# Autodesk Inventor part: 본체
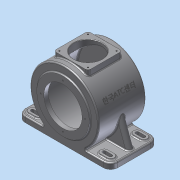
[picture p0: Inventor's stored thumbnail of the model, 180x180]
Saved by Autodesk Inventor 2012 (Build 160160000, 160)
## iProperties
Created: 2015-06
Part Number: 본체
Material: Default
Document SubType Name: Modeling
Designer: Administrator
Density: 1 g/cm^3
Author: Administrator
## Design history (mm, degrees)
sketch "스케치1"
  geometry: C1 r 85 at (0, 0); 1 further point
  constraints: 1 centre point, 1 coincident
  dimensions: "d0" = 170 diameter of C1
extrude "돌출1" new body sketch "스케치1" stored distance "d1" = 118; taper "d2" = 0 deg
node "작업 평면1"
sketch "스케치2"
  geometry: L1 (-115, 59)-(115, 59); L2 (115, 59)-(115, -59); L3 (115, -59)-(-115, -59); L4 (-115, -59)-(-115, 59); L5 (-115, -59)-(115, 59); 2 further points
  constraints: 10 end point, 2 parallel, 1 coincident, 1 horizontal, 1 midpoint, 1 perpendicular
  dimensions: "d4" = 118 distance between parallel lines of L3 L1; "d5" = 230 distance between parallel lines of L2 L4
extrude "돌출2" join sketch "스케치2" distance "d6" = 14; taper "d7" = 0 deg
node "작업 평면2"
sketch "스케치4"
  geometry: C1 r 77 at (0, 0); 1 further point
  constraints: 1 centre point, 1 coincident
  dimensions: "d12" = 154 diameter of C1
extrude "돌출4" cut sketch "스케치4" distance "d13" = 102; taper "d14" = 0 deg
sketch "스케치5"
  geometry: C1 r 65 at (0, 0); A1 r 85 centre (0, 0) between (71, 46.733) and (71, -46.733) reference
  constraints: 1 centre point, 1 coincident
  dimensions: "d15" = 130 diameter of C1
extrude "돌출5" join sketch "스케치5" distance "d16" = 3; taper "d17" = 0 deg
sketch "스케치6"
  geometry: C1 r 65 at (0, 0) reference; C2 r 47.5 at (0, 0)
  constraints: 1 centre point, 1 coincident
  dimensions: "d18" = 95 diameter of C2
extrude "돌출6" cut sketch "스케치6" distance "d19" = 11; taper "d20" = 0 deg
sketch "스케치7"
  geometry: C1 r 65 at (0, 0); A1 r 85 centre (0, 0) between (-71, -46.733) and (-71, 46.733) reference
  constraints: 1 centre point, 1 coincident
  dimensions: "d21" = 130 diameter of C1
extrude "돌출7" join sketch "스케치7" distance "d22" = 13; taper "d23" = 0 deg
sketch "스케치8"
  geometry: C1 r 77 at (0, 0) reference; C2 r 31 at (0, 0)
  constraints: 1 centre point, 1 coincident
  dimensions: "d24" = 62 diameter of C2
extrude "돌출8" join sketch "스케치8" distance "d25" = 3.5; taper "d26" = 0 deg
sketch "스케치9"
  geometry: C1 r 31 at (0, 0) reference; C2 r 23.5 at (0, 0)
  constraints: 1 centre point, 1 coincident
  dimensions: "d27" = 47 diameter of C2
extrude "돌출9" cut sketch "스케치9" distance "d28" = 14; taper "d29" = 0 deg
sketch "스케치10"
  geometry: C1 r 23.5 at (0, 0) reference; C2 r 15 at (0, 0)
  constraints: 1 centre point, 1 coincident
  dimensions: "d30" = 30 diameter of C2
extrude "돌출10" cut sketch "스케치10" distance "d31" = 3; taper "d32" = 0 deg
node "작업 평면4"
sketch "스케치11"
  geometry: L1 (-42.5, 42.5)-(42.5, 42.5); L2 (42.5, 42.5)-(42.5, -42.5); L3 (42.5, -42.5)-(-42.5, -42.5); L4 (-42.5, -42.5)-(-42.5, 42.5); L5 (-42.5, 0)-(42.5, 0); L6 (0, 42.5)-(0, -42.5); L7 (-85, 59)-(85, 59) reference; L8 (85, -59)-(85, 59) reference; 3 further points
  constraints: 12 end point, 4 midpoint, 2 parallel, 1 horizontal, 1 perpendicular
  dimensions: "d35" = 85 distance between parallel lines of L3 L1; "d36" = 85 distance between parallel lines of L2 L4; "d37" = 59 distance between parallel lines of L5 L7; "d38" = 85 distance between parallel lines of L6 L8
extrude "돌출11" join sketch "스케치11" stored distance "d39" = 3; taper "d40" = 0 deg
sketch "스케치12"
  geometry: C1 r 35 at (0, 0); 1 further point
  constraints: 1 centre point, 1 coincident
  dimensions: "d41" = 70 diameter of C1
extrude "돌출12" cut sketch "스케치12" stored distance "d42" = 3; taper "d43" = 0 deg
sketch "스케치13"
  geometry: L1 (59, -115)-(59, 115) reference; L2 (-32, 97)-(-32, 81); L3 (-50, 97)-(-50, 81); L4 (50, 97)-(50, 81); L5 (32, 97)-(32, 81); L6 (41, 115)-(41, 46.733); L7 (32, -81)-(32, -97); L8 (50, -81)-(50, -97); L9 (-32, -81)-(-32, -97); L10 (-50, -81)-(-50, -97); L11 (-41, 115)-(-41, 46.733); L12 (-41, 46.733)-(-41, -115); L13 (41, 46.733)-(41, -115); L14 (59, 115)-(-59, 115) reference; L15 (-59, 115)-(-59, -115) reference; L16 (-59, -115)-(59, -115) reference; A1 r 9 centre (-41, 97) between (-32, 97) and (-50, 97); A2 r 9 centre (-41, 81) between (-50, 81) and (-32, 81); A3 r 9 centre (41, 97) between (50, 97) and (32, 97); A4 r 9 centre (-41, -81) between (-32, -81) and (-50, -81); A5 r 9 centre (-41, -97) between (-50, -97) and (-32, -97); A6 r 9 centre (41, -81) between (50, -81) and (32, -81); A7 r 9 centre (41, -97) between (32, -97) and (50, -97); A8 r 9 centre (41, 81) between (32, 81) and (50, 81); 2 further points
  constraints: 24 end point, 16 point on circle, 11 tangent, 8 centre point, 8 point on line, 5 parallel, 4 vertical
  dimensions: "d68" = 16 distance of A2.centre A1.centre; "d69" = 16 distance of A3.centre A8.centre; "d71" = 18 distance from line of A3.centre L1; "d74" = 9 radius of A1; "d75" = 9 radius of A2; "d76" = 18 distance from line of L14 A1.centre; "d77" = 18 distance from line of A1.centre L15; "d78" = 18 distance from line of L14 A3.centre; "d79" = 9 radius of A3; "d80" = 9 radius of A8; "d81" = 9 radius of A4; "d82" = 9 radius of A5; "d84" = 16 distance of A5.centre A4.centre; "d85" = 18 distance from line of L15 A5.centre; "d86" = 9 radius of A7; "d87" = 9 radius of A6; "d88" = 16 distance of A6.centre A7.centre; "d89" = 18 distance from line of L1 A7.centre; "d91" = 18 distance from line of L16 A7.centre; "d92" = 18 distance from line of L16 A5.centre
extrude "돌출13" join sketch "스케치13" distance "d93" = 3; taper "d94" = 0 deg
sketch "스케치14"
  geometry: L1 (-32, 97)-(-32, 81) reference; L2 (-50, 81)-(-50, 97) reference; L3 (-32, -81)-(-32, -97) reference; L4 (-50, -97)-(-50, -81) reference; L5 (50, -81)-(50, -97) reference; L6 (32, -97)-(32, -81) reference; L7 (-45, 97)-(-45, 81); L8 (-37, 97)-(-37, 81); L9 (37, 97)-(37, 81); L10 (45, 97)-(45, 81); L11 (-37, -81)-(-37, -97); L12 (-45, -81)-(-45, -97); L13 (37, -81)-(37, -97); L14 (45, -81)-(45, -97); L15 (-59, 115)-(59, 115) reference; L16 (-59, 46.733)-(-59, 115) reference; L17 (59, 115)-(59, 46.733) reference; L18 (59, -46.733)-(59, -115) reference; L19 (59, -115)-(-59, -115) reference; L20 (-59, -115)-(-59, -46.733) reference; A1 r 9 centre (-41, 97) between (-32, 97) and (-50, 97) reference; A2 r 9 centre (-41, -81) between (-32, -81) and (-50, -81) reference; A3 r 9 centre (-41, 81) between (-50, 81) and (-32, 81) reference; A4 r 9 centre (-41, -97) between (-50, -97) and (-32, -97) reference; A5 r 9 centre (41, -81) between (50, -81) and (32, -81) reference; A6 r 9 centre (41, -97) between (32, -97) and (50, -97) reference; A7 r 4 centre (-41, 81) between (-45, 81) and (-37, 81); A8 r 4 centre (-41, 97) between (-37, 97) and (-45, 97); A9 r 4 centre (41, 81) between (37, 81) and (45, 81); A10 r 4 centre (41, 97) between (45, 97) and (37, 97); A11 r 4 centre (-41, -97) between (-45, -97) and (-37, -97); A12 r 4 centre (-41, -81) between (-37, -81) and (-45, -81); A13 r 4 centre (41, -97) between (37, -97) and (45, -97); A14 r 4 centre (41, -81) between (45, -81) and (37, -81); 11 further points
  constraints: 16 end point, 16 point on circle, 15 tangent, 8 centre point, 8 coincident, 1 parallel
  dimensions: "d110" = 4 radius of A8; "d111" = 4 radius of A7; "d112" = 16 distance of A3.centre point (-41, 97); "d113" = 18 distance from line of L15 point (-41, 97); "d114" = 18 distance from line of L16 point (-41, 81); "d115" = 5 radial gap between concentric circles of A7 A3; "d116" = 4 radius of A10; "d117" = 4 radius of A9; "d118" = 16 distance of point (41, 97) point (41, 81); "d119" = 18 distance from line of point (41, 97) L15; "d120" = 18 distance from line of L17 point (41, 97); "d121" = 18 distance from line of L17 point (41, 81); "d122" = 4 radius of A14; "d123" = 4 radius of A13; "d124" = 18 distance from line of L18 point (41, -81); "d125" = 16 distance of point (41, -81) A6.centre; "d126" = 18 distance from line of L19 point (41, -97); "d127" = 5 radial gap between concentric circles of A6 A13; "d128" = 4 radius of A12; "d129" = 4 radius of A11; "d130" = 16 distance of point (-41, -97) point (-41, -81); "d131" = 18 distance from line of L20 point (-41, -97); "d132" = 18 distance from line of L19 point (-41, -97); "d133" = 5 radial gap between concentric circles of A2 A12
extrude "돌출14" cut sketch "스케치14" stored distance "d134" = 3; taper "d135" = 0 deg
node "작업 평면5"
sketch "스케치15"
  geometry: L1 (71, 115)-(71, 46.733) reference; L2 (85, 115)-(71, 115) reference; L3 (71, -115)-(71, -46.733) reference; L4 (85, -115)-(71, -115) reference; L5 (71, 115)-(71, 109); L6 (71, 109)-(4.703, 84.87); L7 (71, -115)-(71, -109); L8 (71, -109)-(4.703, -84.87); A1 r 85 centre (0, 0) between (71, 46.733) and (71, -46.733) reference; 1 further point
  constraints: 8 end point, 2 point on circle, 2 point on line
  dimensions: "d137" = 6 distance of L1.start L5.end; "d138" = 110 deg angle of L5 L6; "d139" = 6 distance of L3.start L7.end; "d140" = 110 deg angle of L8 L7
extrude "돌출15" join sketch "스케치15" stored distance "d141" = 15; taper "d142" = 0 deg
node "작업 평면7"
  node "작업 평면6"
sketch "스케치16"
  geometry: 2 further points
  constraints: 1 coincident, 1 other
feature "엠보싱1" sketch "스케치16" dims "d145" = 0.5, "d146" = 0
sketch "스케치17"
  geometry: L1 (42.5, 42.5)-(42.5, -42.5) reference; L2 (-42.5, 42.5)-(42.5, 42.5) reference; L3 (-35.5, 35.5)-(35.5, 35.5); L4 (35.5, 35.5)-(35.5, -35.5); L5 (35.5, -35.5)-(-35.5, -35.5); L6 (-35.5, -35.5)-(-35.5, 35.5); 4 further points
  constraints: 8 end point, 4 coincident, 2 parallel, 1 horizontal, 1 perpendicular
  dimensions: "d147" = 71 distance between parallel lines of L5 L3; "d148" = 71 distance between parallel lines of L6 L4; "d149" = 7 distance between parallel lines of L4 L1; "d150" = 7 distance between parallel lines of L3 L2
hole "구멍1" sketch "스케치17" at (-35.5, 35.5), (35.5, 35.5), (35.5, -35.5), (-35.5, -35.5) diameter "d151" = 3.242; stored, may be unused: countersink angle "d155" = 90 deg, drill point angle "d157" = 118 deg; dims "d152" = 10, "d153" = 4, "d154" = 2, "d156" = 13
sketch "스케치18"
  geometry: L1 (0, 55)-(0, -55); L2 (-55, 0)-(55, 0); C1 r 65 at (0, 0) reference; A1 r 55 centre (0, 0) between (0, 55) and (0, -55); 5 further points
  constraints: 5 coincident, 4 end point, 4 point on circle, 2 midpoint, 1 centre point, 1 perpendicular, 1 vertical
  dimensions: "d158" = 110 diameter of A1
hole "구멍2" sketch "스케치18" at (0, 55), (55, 0), (0, -55), (-55, 0) diameter "d159" = 3.242; stored, may be unused: countersink angle "d163" = 90 deg, drill point angle "d165" = 0 deg; dims "d160" = 10, "d161" = 4, "d162" = 2, "d164" = 13
fillet "모깎기1"
fillet "모깎기2"
fillet "모깎기3" dims "d166" = 0.3
feature "면 기울기1" dims angle "d167" = 25 deg
chamfer "모따기1" distance "d168" = 1; stored, may be unused: second distance "d169" = 2, angle "d170" = 45 deg
chamfer "모따기2" distance "d171" = 1; stored, may be unused: second distance "d172" = 2, angle "d173" = 45 deg
fillet "모깎기4" dims "d174" = 7
fillet "모깎기5" dims "d175" = 3
fillet "모깎기6" dims "d176" = 3
fillet "모깎기7" dims "d177" = 3
fillet "모깎기8" dims "d178" = 3
fillet "모깎기11" dims "d181" = 3
fillet "모깎기13" dims "d183" = 18
fillet "모깎기14" dims "d184" = 3
fillet "모깎기15" dims "d185" = 3
fillet "모깎기16" dims "d186" = 3
fillet "모깎기17" dims "d187" = 3
node "솔리드1"
node "작업축1"
other parameters: "d3" = 85, "d11" = 51, "d34" = -88, "d136" = 0, "d143" = -25 deg, "d144" = 85.5
